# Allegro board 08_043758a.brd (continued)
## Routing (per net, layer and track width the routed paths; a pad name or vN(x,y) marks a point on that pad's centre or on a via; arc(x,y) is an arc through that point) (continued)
IO_L20_34_TX_D10: length 22.9
  TOP w0.102: v2(48.22,33.34) 48.23,33.35 U4.R8 ; U5.F8 v2(30.74,30.48)
  L6_SIG w0.114: v2(30.74,30.48) 30.75,30.48 31.14,30.88 31.14,31.68 31.48,32.02 31.68,32.02 32.14,32.48 35.15,32.48 35.89,33.22 44.51,33.22 45.06,32.68 45.06,32.28 45.19,32.15 47.79,32.15 48.06,31.88 48.36,31.88 48.76,32.28 48.76,32.8 v2(48.22,33.34)
IO_L20_34_TX_D11: length 22.6
  TOP w0.102: U5.E7 v2(31.54,31.28) ; v2(44.53,32.55) 46.03,34.05 48.23,34.05 48.32,34.15 U4.R7
  L6_SIG w0.114: v2(31.54,31.28) 31.54,31.68 31.65,31.78 31.85,31.78 32.31,32.24 35.73,32.24 35.87,32.38 35.87,32.54 36.02,32.68 36.23,32.68 36.37,32.54 36.37,32.38 36.52,32.24 36.72,32.24 36.87,32.38 36.87,32.54 37.01,32.68 37.22,32.68 37.36,32.54 37.36,32.38 37.51,32.24 37.71,32.24 37.86,32.38 37.86,32.54 38,32.68 38.21,32.68 38.35,32.54 38.35,32.38 38.5,32.24 38.7,32.24 38.85,32.38 38.85,32.54 38.99,32.68 39.2,32.68 39.34,32.54 39.34,32.26 39.49,32.11 39.69,32.11 39.84,32.26 39.84,32.54 39.98,32.68 40.19,32.68 40.33,32.54 40.33,32.24 40.49,32.08 44.4,32.08 44.53,32.21 v2(44.53,32.55)
IO_L21_34_CTRL_OUT4: length 32.1
  TOP w0.102: U5.F6 v2(29.95,32.88) ; U4.M10 v2(50.73,31.35)
  L5_SIG w0.114: v2(50.73,31.35) 51.13,30.95 51.13,30.34 50.93,30.14 48.93,30.14 48.26,29.47 46.91,29.47 45.93,30.45 45.53,30.45 44.02,31.95 44.02,32.85 43.26,33.61 43.26,34.38 41.27,36.38 36.57,36.38 35.28,37.67 32.1,37.67 31.6,37.16 31.6,36.73 31.14,36.28 31.14,33.47 30.95,33.28 30.35,33.28 v2(29.95,32.88)
IO_L21_34_CTRL_OUT5: length 30.6
  TOP w0.102: U4.M11 v2(50.73,30.55) ; U5.F5 v2(29.95,33.67)
  L5_SIG w0.114: v2(29.95,33.67) 30.34,34.07 30.34,34.68 29.95,35.08 29.95,36.65 31.72,38.43 40.55,38.43 45.23,33.75 45.23,32.31 45.69,31.85 46.33,31.85 47.03,31.15 47.03,30.88 47.36,30.54 47.93,30.54 48.34,30.95 50.33,30.95 v2(50.73,30.55)
IO_L22_34_CTRL_OUT6: length 32.3
  TOP w0.102: U5.F4 v2(29.94,34.48) ; v2(49.93,34.55) U4.N7
  L5_SIG w0.114: v2(29.94,34.48) 29.54,34.08 28.85,34.08 28.74,34.18 28.74,37.1 29.18,37.54 29.69,37.54 31.34,39.19 40.79,39.19 47.03,32.95 47.03,32.38 47.26,32.14 48.43,32.14 48.76,32.48 48.76,33.38 v2(49.93,34.55)
IO_L22_34_CTRL_OUT7: length 29.9
  TOP w0.102: v2(49.93,33.75) U4.N8 ; U5.G4 v2(29.14,34.48)
  L5_SIG w0.114: v2(29.14,34.48) 29.55,34.88 29.55,36.76 31.6,38.81 40.67,38.81 46.23,33.25 46.23,32.35 47.23,31.34 48.33,31.34 49.53,32.54 49.53,33.35 v2(49.93,33.75)
IO_L23_35_SPI_CLK: length 70.5
  TOP w0.102: U5.J5 v2(27.55,33.68) ; U4.E11 v2(57.13,30.55)
  L5_SIG w0.114: v2(27.55,33.68) 27.15,33.28 26.44,33.28 26.04,33.68 24.96,33.68 21.91,30.62 21.91,23.61 28.17,17.35 34.52,17.35 35.28,16.58 44.55,16.58 45.18,17.22 57.63,17.22 58.83,18.42 58.83,25.95 59.33,26.45 59.33,28.05 59.13,28.25 59.13,30.07 58.14,31.06 57.64,31.06 v2(57.13,30.55)
IO_L23_35_SPI_ENB: length 63.4
  TOP w0.102: U4.E12 v2(57.13,29.75) ; U5.K6 v2(26.74,32.88)
  L5_SIG w0.114: v2(57.13,29.75) 57.13,29.75 57.53,29.35 58.13,29.35 58.33,29.15 58.33,27.95 58.73,27.55 58.73,26.85 58.23,26.35 58.23,18.96 57.25,17.98 28.55,17.98 22.51,24.02 22.51,30.37 24.61,32.48 26.34,32.48 v2(26.74,32.88)
IO_L24_35_SPI_DI: length 64.3
  TOP w0.102: U4.E13 v2(57.13,28.95) ; U5.J4 v2(27.54,34.48)
  L5_SIG w0.114: v2(57.13,28.95) 57.13,28.95 57.93,28.15 57.93,19.17 57.12,18.36 28.67,18.36 22.8,24.24 22.8,30.24 22.99,30.43 23.2,30.43 23.42,30.21 23.63,30.21 23.77,30.35 23.77,30.56 23.55,30.78 23.55,30.99 24.21,31.65 26.31,31.65 26.61,31.94 27.51,31.94 27.94,32.38 U5.J4 v2(27.54,34.48)
IO_L24_35_SPI_DO: length 66.7
  TOP w0.102: U4.F12 v2(56.33,29.75) ; U5.L6 v2(25.95,32.88)
  L5_SIG w0.114: v2(25.95,32.88) 25.55,33.28 24.99,33.28 22.21,30.5 22.21,23.81 28.42,17.6 36.93,17.6 37.56,16.96 44.17,16.96 44.8,17.6 57.38,17.6 58.53,18.76 58.53,26.15 59.03,26.65 59.03,27.75 58.63,28.15 58.63,29.25 58.33,29.55 58.33,29.95 58.13,30.15 56.73,30.15 56.33,29.75 v2(56.33,29.75)
JTAG_TCK: length 44.5
  TOP w0.102: v1(70.34,31.82) 69.83,32.33 63.98,32.33 63.47,32.84 61.55,32.84 61.44,32.95 55.53,32.95 U4.G9 ; P1.4 66.01,9.34 v1(68.82,9.34)
  L5_SIG w0.114: v1(68.82,9.34) 68.82,19.14 69.83,20.15 69.83,31.32 v1(70.34,31.82)
JTAG_TDI: length 38.9
  TOP w0.102: U4.L7 v2(51.53,34.55)
  L5_SIG w0.114: P1.8 65,9.09 62.58,9.09 61.85,9.83 61.85,23.42 61.06,24.2 61.06,31.06 59.07,33.05 55.63,33.05 54.53,34.15 51.92,34.15 51.53,34.54 v2(51.53,34.55)
JTAG_TDO: length 37.5
  TOP w0.102: U4.L8 v2(51.53,33.75)
  L5_SIG w0.114: v2(51.53,33.75) 51.53,33.74 51.92,33.35 54.93,33.35 55.53,32.75 58.93,32.75 59.93,31.75 59.93,30.27 60.23,29.97 60.23,29.49 60.68,29.04 60.68,23.95 61.47,23.16 61.47,9.45 62.33,8.58 64.23,8.58 P1.6
JTAG_TMS: length 34.5
  TOP w0.102: U4.L9 v2(51.53,32.95)
  L5_SIG w0.114: v2(51.53,32.95) 52.73,31.75 59.13,31.75 59.53,31.35 59.53,30.31 59.92,29.93 59.92,29.22 60.3,28.84 60.3,23.7 61.09,22.91 61.09,9.19 P1.2
PG_1P0V: length 28.6
  TOP w0.203: U6.28 v2(93.7,46.94)
  TOP w0.305: U3.16 92.57,21.55 v1(92.94,21.92)
  L6_SIG w0.254: v1(92.94,21.92) 93.7,22.68 93.7,46.93 v2(93.7,46.94)
  BOTTOM w0.305: R6.2 v1(92.94,21.92)
PG_1P8V: length 12.7
  TOP w0.203: U6.29 94.2,47.27 v2(94.32,46.92) ; U6.13 v2(93.7,54.05)
  L5_SIG w0.305: v2(94.32,46.92) 94.32,47.3 96.11,49.1 96.11,52.52 95.48,53.16 94.21,53.16 93.7,53.66 v2(93.7,54.05)
  BOTTOM w0.305: v2(94.32,46.92) R59.1
PS-SRST#: length 30.4
  TOP w0.127: v1(71.23,29.41) 70.09,29.41 68.57,30.93 64.11,30.93 63.98,30.81 63.98,30.54 R74.2 61.95,30.3 60.91,31.34 59.52,31.34 U4.B11
  L5_SIG w0.127: v1(74.65,42.75) 75.54,41.86 75.54,33.08 71.87,29.41 v1(71.23,29.41)
  BOTTOM w0.127: R11.2 v1(74.65,42.75)
PS_MIO01_500_QSPI0_SS_B: length 37
  TOP w0.127: U13.C2 v2(72.61,48.31) ; U4.A5 60.54,35.75 61.31,36.52 65.25,36.52 65.89,37.16 v1(65.89,40.08)
  L5_SIG w0.127: v1(65.89,40.08) 68.81,43 68.81,49.98 69.06,50.24 69.44,50.24 69.59,50.09 69.59,48.99 69.74,48.84 69.95,48.84 70.1,48.99 70.1,50.09 70.25,50.24 70.46,50.24 70.61,50.09 70.61,48.99 70.76,48.84 70.97,48.84 71.11,48.99 71.11,50.09 71.26,50.24 71.47,50.24 71.62,50.09 71.62,48.74 71.77,48.59 71.98,48.59 72.13,48.74 72.13,50.09 72.28,50.24 73.25,50.24 73.63,49.86 73.63,49.33 v2(72.61,48.31)
  BOTTOM w0.127: R14.2 72.62,48.32 v2(72.61,48.31)
PS_MIO02_500_QSPI0_IO0: length 33.4
  TOP w0.127: U4.A8 61.43,33.35 61.56,33.22 63.73,33.22 63.85,33.35 69.71,33.35 70.47,32.59 73.12,32.59 v1(74.14,33.6) ; U13.D3 v2(70.61,47.31)
  L5_SIG w0.127: v2(70.61,47.31) 72.24,45.68 72.24,41.98 72.47,41.75 72.68,41.75 72.91,41.98 73.13,41.98 73.27,41.83 73.27,41.62 73.04,41.39 73.04,41.18 73.27,40.95 73.48,40.95 73.65,41.12 73.86,41.12 74.01,40.97 74.01,40.76 73.84,40.59 73.84,40.38 74.14,40.08 v1(74.14,33.6)
  BOTTOM w0.127: v2(70.61,47.31) 69.93,47.31 R120.1
PS_MIO03_500_QSPI0_IO1: length 38
  TOP w0.127: U4.A7 60.36,33.72 v2(61.65,33.72) ; U13.D2 v2(70.61,48.31)
  L5_SIG w0.127: v2(70.61,48.31) 69.54,48.31 69.19,47.95 69.19,47.59 69.34,47.44 69.8,47.44 69.95,47.29 69.95,47.08 69.8,46.93 69.34,46.93 69.19,46.78 69.19,41.92 69.04,41.77 68.32,41.77 68.17,41.62 68.17,41.41 68.32,41.26 69.04,41.26 69.19,41.11 69.19,40.9 69.04,40.75 68.32,40.75 68.17,40.6 68.17,40.39 68.32,40.24 69.04,40.24 69.19,40.1 69.19,39.82 68.81,39.44 67.66,39.44 66.77,38.55 66.77,38.09 68.02,36.84 68.02,36.63 67.87,36.48 67.66,36.48 66.41,37.73 66.2,37.73 66.05,37.58 66.05,37.37 66.67,36.75 66.67,36.54 66.52,36.39 66.31,36.39 65.69,37.01 65.48,37.01 65.33,36.86 65.33,36.65 65.95,36.03 65.95,35.82 65.8,35.67 65.59,35.67 64.97,36.29 64.76,36.29 64.61,36.14 64.61,35.93 65.23,35.32 65.23,35.1 65.08,34.96 64.87,34.96 64.26,35.57 64.05,35.57 63.09,34.62 61.95,34.62 61.65,34.32 v2(61.65,33.72)
  BOTTOM w0.127: R119.1 69.91,48.31 v2(70.61,48.31)
PS_MIO04_500_QSPI0_IO2: length 35.9
  TOP w0.127: U4.C8 v2(57.93,33.75) ; U13.C4 v2(71.59,45.29)
  L5_SIG w0.127: v2(71.59,45.29) 70.97,45.92 70.46,45.92 69.57,45.03 69.57,42.36 70.08,41.86 70.08,37.67 69.66,37.25 69.66,37.04 70.4,36.3 70.4,36.09 70.25,35.94 70.04,35.94 69.3,36.68 69.09,36.68 68.91,36.5 68.91,36.29 69.59,35.61 69.59,35.4 69.44,35.25 69.23,35.25 68.55,35.93 68.34,35.93 68.19,35.78 68.19,35.57 68.87,34.89 68.87,34.68 68.72,34.53 68.51,34.53 67.83,35.21 67.62,35.21 67.47,35.06 67.47,34.85 68.15,34.17 68.15,33.96 68,33.81 67.79,33.81 67.11,34.49 64.11,34.49 62.84,33.22 61.31,33.22 60.17,34.36 58.54,34.36 v2(57.93,33.75)
  BOTTOM w0.127: v2(71.59,45.29) 71.6,45.29 R121.1
PS_MIO05_500_QSPI0_IO3: length 68.4
  TOP w0.127: v1(70.34,30.93) 69.33,31.95 63.85,31.95 63.26,32.55 U4.A9 ; P1.5 v1(65.38,4.65) ; U13.D4 v2(70.61,45.31)
  L5_SIG w0.127: v2(70.61,45.31) 69.95,44.65 69.95,42.62 70.37,42.2 71.13,42.2 71.28,42.05 71.28,41.84 70.86,41.41 70.86,41.2 71.01,41.06 71.22,41.06 71.64,41.48 71.85,41.48 72,41.33 72,41.12 71.57,40.7 71.57,40.49 71.72,40.34 71.93,40.34 72.36,40.76 72.57,40.76 72.72,40.61 72.72,40.4 72.29,39.98 72.29,39.77 72.47,39.59 72.68,39.59 73.17,40.07 73.38,40.07 73.53,39.93 73.53,39.72 73.04,39.23 73.04,39.02 73.63,38.43 73.63,33.14 72.54,32.05 71.46,32.05 v1(70.34,30.93) 70.34,19.77 69.31,18.74 69.31,9.99 69.71,9.6 69.71,5.28 69.07,4.65 v1(65.38,4.65)
  BOTTOM w0.127: R122.1 70.61,44.54 v2(70.61,45.31)
PS_MIO06_500_QSPI0_SCLK: length 34.4
  TOP w0.127: v1(72.12,30.93) 71.23,30.05 69.96,30.05 68.82,31.19 63.6,31.19 63.04,31.75 U4.A10 ; U13.B2 v2(73.61,48.31)
  L5_SIG w0.127: v1(72.12,30.93) 74.65,33.46 74.65,41.22 72.74,43.13 72.74,47.44 v2(73.61,48.31)
  BOTTOM w0.127: R116.1 73.61,49.08 v2(73.61,48.31)
PS_MIO07_500_USB_RESET_B: length 20.5
  TOP w0.127: U4.A12 v2(60.58,30.15) ; v1(76.05,30.81) 77.3,29.55 U15.27
  L6_SIG w0.127: v1(76.05,30.81) 73.12,30.81 72.74,30.43 61.57,30.43 61.29,30.15 v2(60.58,30.15)
  BOTTOM w0.127: v2(60.58,30.15) 60.02,30.15 R76.2
PS_MIO28_501_USB0_D4: length 23.7
  TOP w0.102: v1(66.65,24.58) 66.39,24.84 66.14,24.84 64.11,26.87 61.44,26.87 60.56,27.75 U4.A15 ; v1(73.25,24.48) U15.7
  L6_SIG w0.114: v1(73.25,24.48) 73.74,24.97 74.14,24.97 74.27,24.84 74.27,24.33 73.25,23.31 65.5,23.31 65.25,23.57 65.25,24.46 65.5,24.71 65.76,24.71 66.01,24.46 66.01,24.08 66.14,23.95 66.52,23.95 66.65,24.08 v1(66.65,24.58)
PS_MIO29_501_USB0_DIR: length 24.6
  TOP w0.102: v1(74.27,30.17) 75.3,29.14 U15.31 ; U4.D11 v2(57.93,30.55)
  L6_SIG w0.114: v2(57.93,30.55) 59.9,30.55 60.17,30.28 60.17,29.88 61.14,28.9 63.41,28.9 63.56,28.76 63.56,28.29 63.7,28.14 63.91,28.14 64.05,28.29 64.05,28.76 64.2,28.9 64.4,28.9 64.55,28.76 64.55,28.29 64.69,28.14 64.9,28.14 65.04,28.29 65.04,28.76 65.19,28.9 65.39,28.9 65.54,28.76 65.54,28.29 65.68,28.14 65.89,28.14 66.03,28.29 66.03,28.76 66.18,28.9 70.2,28.9 70.58,28.52 71.35,28.52 73,30.17 v1(74.27,30.17)
PS_MIO30_501_USB0_STP: length 25.2
  TOP w0.102: v1(67.41,23.95) 66.52,23.95 63.98,26.49 61.31,26.49 60.55,27.25 59.62,27.25 U4.B15 ; U15.29 76.3,29.53 75.66,30.17 v1(75.28,30.17)
  L6_SIG w0.114: v1(67.41,23.95) 67.79,23.95 68.04,23.7 71.6,23.7 72.74,24.84 72.74,25.85 73.25,26.36 74.01,26.36 75.28,27.63 v1(75.28,30.17)
PS_MIO31_501_USB0_NXT: length 23.6
  TOP w0.102: U15.2 73.4,26.98 v1(72.87,27.51) ; U4.C12 v2(58.73,29.75)
  L6_SIG w0.114: v1(72.87,27.51) 72.36,28.01 66.39,28.01 66.01,27.63 65.52,27.63 65.38,27.49 65.38,26.89 65.23,26.74 65.03,26.74 64.88,26.89 64.88,27.49 64.74,27.63 64.53,27.63 64.39,27.49 64.39,26.89 64.24,26.74 64.04,26.74 63.89,26.89 63.89,27.49 63.75,27.63 63.54,27.63 63.4,27.49 63.4,26.89 63.25,26.74 63.05,26.74 62.9,26.89 62.9,27.49 62.76,27.63 62.55,27.63 62.41,27.49 62.41,26.89 62.26,26.74 62.06,26.74 61.91,26.89 61.91,27.49 61.77,27.63 60.04,27.63 58.73,28.95 v2(58.73,29.75)
PS_MIO32_501_USB0_D0: length 24.3
  TOP w0.102: v1(64.74,23.44) 63.22,24.97 60.55,24.97 60.3,25.22 58.39,25.22 56.73,26.88 U4.E15 ; v1(71.98,27.47) 71.98,26.71 72.21,26.48 U15.3
  L6_SIG w0.114: v1(64.74,23.44) 64.74,24.46 65.76,25.47 66.65,25.47 67.03,25.85 67.03,26.36 66.52,26.87 66.52,27.25 66.74,27.47 v1(71.98,27.47)
PS_MIO33_501_USB0_D1: length 24
  TOP w0.102: U4.C11 58.74,30.54 60.69,30.54 60.72,30.52 60.73,30.52 60.95,30.3 60.95,30.29 61.95,29.28 63.98,29.28 64.23,29.03 65.89,29.03 67.53,27.39 v1(67.53,26.1) ; U15.4 71.73,25.98 v1(71.22,26.49)
  L6_SIG w0.114: v1(67.53,26.1) 67.53,26.99 67.66,27.12 67.89,27.12 68.03,26.98 68.03,26.51 68.18,26.36 68.39,26.36 68.53,26.51 68.53,26.98 68.68,27.12 68.88,27.12 69.03,26.98 69.03,26.51 69.17,26.36 69.38,26.36 69.52,26.51 69.52,26.98 69.67,27.12 69.95,27.12 70.08,27 70.08,26.36 70.2,26.24 70.46,26.24 70.58,26.36 70.58,26.87 70.84,27.12 71.09,27.12 71.22,27 v1(71.22,26.49)
PS_MIO34_501_USB0_D2: length 25.3
  TOP w0.102: v1(65.38,22.43) 65.38,23.57 63.6,25.35 60.93,25.35 60.17,26.11 58.29,26.11 57.53,26.87 U4.D15 ; v1(73.25,25.48) U15.5
  L6_SIG w0.114: v1(65.38,22.43) 65.89,22.93 74.39,22.93 74.7,23.24 74.7,25.17 74.39,25.48 v1(73.25,25.48)
PS_MIO35_501_USB0_D3: length 23.7
  TOP w0.102: v1(71.22,25.47) 71.72,24.98 U15.6 ; U4.A14 60.78,28.55 61.69,27.63 64.36,27.63 66.39,25.6 68.3,25.6 v1(68.81,25.09)
  L6_SIG w0.114: v1(68.81,25.09) 68.3,25.09 68.04,25.35 68.04,25.73 68.17,25.85 69.31,25.85 69.44,25.73 69.44,24.84 69.57,24.71 69.94,24.71 70.08,24.86 70.08,25.71 70.23,25.85 70.43,25.85 70.58,25.71 70.58,24.86 70.72,24.71 71.47,24.71 71.98,25.22 71.98,25.83 71.83,25.98 71.35,25.98 71.22,25.85 v1(71.22,25.47)
PS_MIO36_501_USB0_CLK: length 23.1
  TOP w0.102: v1(67.41,25.09) 66.77,25.09 66.65,25.22 66.27,25.22 64.23,27.25 61.57,27.25 60.68,28.14 59.54,28.14 U4.B14 ; U15.1 v1(74.1,28.14)
  L6_SIG w0.114: v1(67.41,25.09) 68.43,24.08 68.76,24.08 69.01,24.33 69.25,24.33 69.5,24.08 69.75,24.08 70,24.33 70.24,24.33 70.5,24.08 71.35,24.08 72.36,25.09 72.36,26.49 72.62,26.74 73.89,26.74 74.9,27.76 74.9,28.52 74.78,28.65 74.23,28.65 74.1,28.52 v1(74.1,28.14)
PS_MIO37_501_USB0_D5: length 24.4
  TOP w0.102: v1(66.39,22.43) 66.39,23.57 63.85,26.11 61.19,26.11 60.42,26.87 59.15,26.87 58.7,27.33 58.7,28.18 U4.C14 ; v1(74.14,22.43) 74.52,22.43 74.8,22.71 U15.9
  L6_SIG w0.114: v1(74.14,22.43) 73.34,22.43 73.19,22.28 73.19,21.94 73.05,21.79 72.84,21.79 72.7,21.94 72.7,22.28 72.55,22.43 72.35,22.43 72.2,22.28 72.2,21.94 72.06,21.79 71.85,21.79 71.71,21.94 71.71,22.28 71.56,22.43 71.36,22.43 71.21,22.28 71.21,21.94 71.07,21.79 70.86,21.79 70.72,21.94 70.72,22.28 70.57,22.43 70.37,22.43 70.22,22.28 70.22,21.94 70.08,21.79 67.54,21.79 66.9,22.43 v1(66.39,22.43)
PS_MIO38_501_USB0_D6: length 25.5
  TOP w0.102: U4.A13 60.33,28.95 60.89,28.95 61.82,28.01 64.62,28.01 v1(66.52,26.11) ; U15.10 75.3,22.57 v1(74.14,21.41)
  L6_SIG w0.114: v1(66.52,26.11) 65.89,26.11 64.23,24.46 64.23,22.55 64.87,21.92 66.65,21.92 67.16,21.41 v1(74.14,21.41)
PS_MIO39_501_USB0_D7: length 25.5
  TOP w0.102: U4.D14 57.96,28.12 57.96,27 58.47,26.49 60.3,26.49 61.06,25.73 63.73,25.73 65.89,23.57 65.89,21.92 v1(66.39,21.41) ; U15.13 76.8,22.53 v1(76.58,22.3)
  L6_SIG w0.114: v1(76.58,22.3) 75.18,20.9 66.9,20.9 v1(66.39,21.41)
PWR_GD: length 23.9
  TOP w0.203: v1(23.23,9.85) R5.2 22.58,10.61 22.28,10.91 U1.5 ; U7.5 v1(43.15,10.23)
  BOTTOM w0.127: v1(23.23,9.85) 28.93,9.85 29.69,9.09 42,9.09 v1(43.15,10.23)
PWR_GD_1.35V: length 59.4
  TOP w0.127: U4.C9 58.73,32.15 63.15,32.15 63.73,31.57 68.95,31.57 70.09,30.43 70.72,30.43 v1(71.23,30.93)
  TOP w0.203: v2(94.33,54.05) 94.2,53.66 U6.12
  L5_SIG w0.127: v2(94.33,54.05) 93.86,54.52 92.21,54.52 91.15,53.46 88.85,53.46 85.17,49.78 85.17,46.58 76.05,37.45 76.05,32.85 71.94,28.74 71.04,28.74 70.74,29.04 70.74,29.85 71.23,30.34 v1(71.23,30.93)
  BOTTOM w0.127: R13.2 72.95,32.01 C47.1 71.52,32.01 R15.1 71.23,31.7 v1(71.23,30.93)
REF_CLK_SG: length 81.4
  TOP w0.127: R50.1 23.21,21.14 v1(23.21,19.38) ; R10.1 63.36,35.63 v1(66.52,35.63)
  BOTTOM w0.127: v1(66.52,35.63) 67.61,34.54 74.47,34.54 74.78,34.24 74.78,25.09 65.76,16.08 46.99,16.08 44.19,18.87 37.44,18.87 36.8,18.23 26.9,18.23 25.75,19.38 v1(23.21,19.38)
RX1A_N: length 2.6
  TOP w0.229: C133.2 arc(23.54,36.54) 23.84,36.45 24.33,36.09 arc(24.64,35.93) 24.99,35.87 25.18,35.87 arc(25.38,35.82) U5.M2
RX1A_P: length 2.5
  TOP w0.229: C134.2 arc(23.72,37.31) 23.71,37.23 arc(23.76,37.06) 23.87,36.93 24.57,36.42 arc(24.77,36.32) 24.99,36.28 25.35,36.28 arc(25.49,36.34) U5.M1
SCL: length 45.4
  TOP w0.102: v2(49.53,26.05) 50.25,26.77 50.52,26.77 50.73,26.98 50.73,28.15 U4.M14
  TOP w0.127: v1(51.03,16.58) 51.53,17.09 52.55,17.09 52.93,16.71 52.93,15.34 55.24,13.03 56.6,13.03 R79.2 57.29,13.61 U11.2 60.24,13.61 60.81,14.17 60.81,15.19 64.23,18.62 65,18.62 v1(65.5,19.12)
  BOTTOM w0.127: v1(51.03,16.58) 51.03,22.93 50.23,23.73 50.23,25.34 49.53,26.04 v2(49.53,26.05) ; v1(65.5,19.12) 65.5,20.27 64.36,21.41 63.22,21.41 61.31,23.31 61.31,26.87 R86.2
SDA: length 44.5
  TOP w0.102: U4.N14 49.93,28.15 49.93,27.25 v2(49.53,26.85)
  TOP w0.127: v1(65.5,18.11) 64.36,18.11 61.31,15.06 61.31,14.04 60.23,12.96 U11.3 57.81,12.96 57.63,12.77 57.63,12.41 R78.2 56.6,12.65 54.92,12.65 52.23,15.34 v1(52.23,16.58)
  BOTTOM w0.127: v1(52.23,16.58) 51.41,17.41 51.41,23.06 50.63,23.84 50.63,25.75 v2(49.53,26.85) ; v1(65.5,18.11) 64.87,18.74 64.87,20.01 63.85,21.03 62.96,21.03 61.06,22.93 61.06,26.36 60.68,26.74 R85.2
SYNC: length 9.2
  TOP w0.305: 88.37,18.6 U3.9 ; U3.9 U3.10 ; U3.9 88.81,17.85 ; U3.10 U3.11 90.11,17.85 ; U3.10 89.46,17.85
  TOP w0.889: L4.1 88.58,16.9 ; L4.1 88.58,12.71 ; L4.1 89.57,14.81
TX1A_N: length 3.8
  TOP w0.229: L8.2 22.65,29.83 arc(22.91,30.01) 23.22,30.07 23.56,30.07 arc(23.88,30.13) 24.16,30.32 24.79,30.95 arc(24.94,31.05) 25.11,31.08 25.23,31.08 arc(25.33,31.06) 25.42,31 U5.M8
TX1A_P: length 3.8
  TOP w0.229: U5.M7 25.44,31.57 arc(25.35,31.51) 25.23,31.49 25.11,31.49 arc(24.78,31.42) 24.5,31.23 23.87,30.6 arc(23.73,30.51) 23.56,30.47 23.22,30.47 arc(22.91,30.54) 22.64,30.72 L9.2
TX_VCO_1P1V_SUPPLY: length 3.4
  TOP w0.305: U5.B11 v2(33.94,28.08) ; U5.A11 v2(34.74,28.08)
  BOTTOM w0.305: R52.1 C128.1 35.16,28.08 v2(34.74,28.08)
  BOTTOM w0.406: v2(33.94,28.08) v2(34.74,28.08)
UART_RX: length 42.6
  TOP w0.127: U4.C6 v2(57.93,35.35) ; P1.1 61.95,7.06 61.95,8.07 62.84,8.96 v1(62.84,9.73)
  L5_SIG w0.127: v2(57.93,35.35) 57.53,34.95 57.53,33.55 57.73,33.35 59.28,33.35 60.93,31.7 64.87,31.7 66.52,30.05 66.52,27.38 65.5,26.36 65.5,24.23 67.66,22.08 67.66,14.55 67.03,13.92 64.11,13.92 62.84,12.65 v1(62.84,9.73)
UART_TX: length 40.5
  TOP w0.127: U4.B7 v2(59.53,33.75)
  L5_SIG w0.127: v2(59.53,33.75) 59.53,33.75 60.95,32.33 65.38,32.33 67.92,29.79 67.92,28.52 68.3,28.14 68.3,8.71 68.93,8.07 68.93,5.66 68.55,5.28 65,5.28 P1.3
UNNAMED_2_ADP1754_I93_SS: length 1.5
  TOP w0.203: C2.1 23.08,12.21 U1.7
UNNAMED_2_ADP1754_I233_SS: length 1.5
  TOP w0.203: U7.7 44.67,12.21 C12.1
UNNAMED_2_ADP2164_I29_EN: length 13.4
  TOP w0.305: 92.99,20.2 R1.1 ; R1.1 93.44,20.61 ; R1.1 93.9,20.2 ; 90.89,24.2 90.76,24.07 U3.1 ; C13.1 89.46,24.16 U3.3 ; 92.5,20.9 U3.15 U3.14 92.5,20.25
  TOP w0.508: C13.1 89.52,24.2 91.79,24.2 93.95,22.04 93.95,20.9
UNNAMED_2_ADP2164_I29_PVIN1: length 11.6
  TOP w0.305: R1.2 93.9,19.57 ; R1.2 93.44,19.16 ; R1.2 92.99,19.57 ; 91.75,19.16 U3.13 92.5,19.6 ; 91.19,18.6 U3.12 90.76,17.85
  TOP w0.762: L1.2 95.22,17.97 ; L1.2 95.22,15.45 ; L1.2 94.34,16.71
  TOP w1.016: C11.1 92.68,16.28 ; C11.1 91.63,15.38 ; C11.1 93.74,15.38
  BOTTOM w0.305: R6.1 93.58,19.5 v1(94.21,19.5)
UNNAMED_2_ADP2164_I29_RT: length 1.8
  TOP w0.305: v1(90.11,23.57) U3.2
  BOTTOM w0.305: R3.2 90.12,23.56 v1(90.11,23.57)
UNNAMED_2_RES_I251_N2: length 1.4
  BOTTOM w0.305: R4.2 R7.1
UNNAMED_3_ICN25Q256AV2_I26_RESE: length 1.5
  TOP w0.127: v2(74.65,45.27) U13.A4
  BOTTOM w0.127: R11.1 v2(74.65,45.27)
UNNAMED_3_ICXC7Z010_I16_PSCLK50: length 6.8
  TOP w0.127: R10.2 63.17,34.55 58.73,34.55 U4.C7
  TOP w0.305: R12.2 63.46,34.74 R10.2
UNNAMED_3_ICXC7Z010_I16_PSMIO75: length 4.9
  TOP w0.127: U4.D9 v2(57.93,32.15)
  BOTTOM w0.127: R83.2 61.74,32.45 58.23,32.45 v2(57.93,32.15)
UNNAMED_3_ICXC7Z010_I16_PSMIO85: length 8.9
  TOP w0.127: R84.1 66.65,37.03 65.76,36.14 61.57,36.14 60.78,35.35 59.54,35.35 U4.B6
UNNAMED_3_RES_I2_N1: length 2.5
  TOP w0.305: R9.1 71.6,36.15 R8.2 70.15,36.14 Y2.1
UNNAMED_3_RES_I48_N1: length 2.4
  TOP w0.305: R12.1 68.18,34.74 Y2.3
UNNAMED_4_ICMT41K256M16_I98_ZQ: length 4.2
  TOP w0.127: v2(52.82,46.57) 52.82,49.47 U2.L8
  BOTTOM w0.165: R165.1 52.82,45.86 v2(52.82,46.57)
UNNAMED_4_ICTPS51206_I44_S3: length 1.8
  TOP w0.127: U14.7 36.35,53.43 v2(36.24,53.54)
  BOTTOM w0.127: v2(36.24,53.54) 36.55,53.24 36.55,53.02 R222.2
UNNAMED_4_ICTPS51206_I44_S5: length 3.7
  TOP w0.127: v1(34.77,52.14) 35.26,52.63 U14.9
  BOTTOM w0.127: v1(34.77,52.14) 35.15,52.52 35.55,52.52 R221.2
UNNAMED_4_ICTPS51206_I44_VLDOIN: length 2.6
  TOP w0.203: 39.86,52.63 U14.2
  TOP w0.508: R44.2 41.3,51.88 ; R44.2 40.74,52.44 ; R44.2 40.18,51.88
UNNAMED_4_ICTPS51206_I44_VTTSNS: length 3
  TOP w0.203: U14.5 39.51,53.83 v2(39.85,54.18)
  BOTTOM w0.305: R43.2 41.2,54.87 C80.1 39.85,54.49 v2(39.85,54.18)
UNNAMED_4_ICXC7Z010_I26_PSDDR_1: length 3.4
  TOP w0.127: U4.H3 v2(54.73,37.75)
  BOTTOM w0.127: R40.1 54.33,39.76 54.33,38.15 v2(54.73,37.75)
UNNAMED_4_ICXC7Z010_I26_PSDDRVR: length 1.2
  TOP w0.127: U4.J3 v2(53.13,37.75)
  BOTTOM w0.127: v2(53.13,37.75) 53.22,37.66 R41.1
UNNAMED_5_CAP_I17_N1: length 20.5
  TOP w0.305: U4.F7 v2(55.53,34.55)
  L6_SIG w0.305: 58.49,33.19 56.65,33.19 56.36,33.47 56.36,34.24 56.05,34.55 v2(55.53,34.55)
  L6_SIG w0.508: v1(66.66,40.09) 66.66,39.71 65.12,38.17 65.12,36.9 63.09,34.87 63.09,33.86 62.28,33.05 58.63,33.05 58.49,33.19
  BOTTOM w0.305: C98.1 55.84,34.23 v2(55.53,34.55)
  BOTTOM w0.508: C93.1 v1(66.66,40.09)
  BOTTOM w0.635: C93.1 66.66,41.93 E5.2
UNNAMED_5_CAP_I17_N2: length 27
  TOP w0.305: U4.J7 v2(53.93,33.75) U4.H7 ; U4.G8 v2(55.53,33.75) U4.F8 ; U4.F6 v2(56.33,35.35)
  L5_SIG w0.406: v2(55.53,33.75) 56.33,34.55 v2(56.33,35.35)
  L6_SIG w0.305: v2(55.53,33.75) 55.53,33.42 56.23,32.71 58.07,32.71 58.53,32.25 58.73,32.25
  L6_SIG w0.508: 58.73,32.25 62.75,32.25 64.11,33.6 64.11,34.62 66.77,37.28 66.77,38.68 67.65,39.56 v1(67.65,40.08) ; v2(55.53,33.75) v2(53.93,33.75)
  BOTTOM w0.305: C98.2 56.33,35.34 v2(56.33,35.35)
  BOTTOM w0.508: v1(67.65,40.08) C93.2
  BOTTOM w0.635: C93.2 E6.2
UNNAMED_5_DIOLED_I60_N: length 2.7
  TOP w0.127: DS1.C v1(106.78,21.49)
  BOTTOM w0.127: v1(106.78,21.49) 106.44,21.16 R48.1
UNNAMED_5_DIOLED_I62_N: length 2.7
  TOP w0.127: DS2.C v1(106.91,13.11)
  BOTTOM w0.127: R87.1 106.57,12.77 v1(106.91,13.11)
UNNAMED_5_ICXC7Z010_I13_DONE0: length 68.5
  TOP w0.127: U4.M7 v2(50.73,34.55)
  L6_SIG w0.127: v1(101.95,16.58) 99.46,14.09 90.35,14.09 86.25,18.19 86.25,25.64 81.75,30.15 79.55,30.15 76.84,32.85 70.14,32.85 69.04,31.75 53.53,31.75 52.73,32.55 52.73,33.95 52.53,34.15 51.12,34.15 50.73,34.53 v2(50.73,34.55)
  BOTTOM w0.127: v1(101.95,16.58) 101.95,17.65 Q1.1
UNNAMED_5_ICXC7Z010_I13_INITB0: length 8.3
  TOP w0.127: R47.1 64.48,36.9 61.06,36.9 60.3,36.15 57.93,36.15 U4.D5
UNNAMED_5_ICXC7Z010_I13_PROGRAM: length 4
  TOP w0.127: U4.K6 v2(52.33,35.35)
  BOTTOM w0.127: R46.1 51.13,33.44 51.13,34.95 51.53,35.35 52.33,35.35 v2(52.33,35.35)
UNNAMED_5_ICXC7Z010_I13_VCCBATT: length 5.2
  TOP w0.127: U4.E6 v2(57.13,35.35)
  BOTTOM w0.127: v2(57.13,35.35) 57.53,34.94 57.53,34.35 57.73,34.15 59.74,34.15 59.93,33.95 59.93,33.05 R45.2
UNNAMED_5_RES_I61_N2: length 2.6
  BOTTOM w0.127: R48.2 104.25,18.65 Q1.3
UNNAMED_5_RES_I63_N2: length 2.6
  BOTTOM w0.127: R87.2 104.21,12.74 Q4.3
UNNAMED_7_AD9363_I13_RBIAS: length 3.7
  TOP w0.178: 25.14,33.68 25.94,33.68
  TOP w0.305: 25.94,33.68 U5.L4
  TOP w0.406: R49.2 23.6,34.16 arc(24.14,33.8) 24.78,33.68 25.14,33.68
UNNAMED_7_AD9363_I13_XTALN: length 4.5
  TOP w0.203: U5.M12 24.93,27.06 C124.1 24.93,23.57 C123.2
UNNAMED_7_CAP_I22_N2: length 1
  BOTTOM w0.305: C126.2 R51.1
UNNAMED_7_CAP_I30_N1: length 1
  BOTTOM w0.305: C127.1 36.15,26.38 R52.2
UNNAMED_7_CAP_I39_N2: length 2.2
  TOP w0.483: T5.4 arc(19.12,31.31) C132.2
UNNAMED_7_CAP_I40_N2: length 2.2
  TOP w0.483: T5.6 arc(19.12,29.22) C131.2
UNNAMED_7_CAP_I51_N1: length 2.2
  TOP w0.483: T1.4 22.98,38.26 arc(23.15,38.01) C134.1
UNNAMED_7_CAP_I52_N1: length 2.2
  TOP w0.483: C133.1 22.68,36.76 22.18,36.76 arc(21.38,36.86) T1.6
UNNAMED_7_CAP_I53_N1: length 2.8
  TOP w0.203: Y3.3 24.98,20.15 R50.2 24.99,21.93 C123.1
UNNAMED_7_CNBNC5P_I55_CNTR: length 16.7
  TOP w0.483: RX1A.1 8.73,46.39 arc(9.67,46.27) 10.55,45.9 12.3,44.89 T1.3
UNNAMED_7_CNBNC5P_I56_CNTR: length 16.9
  TOP w0.483: T5.3 13.48,31.54 arc(11.3,30.64) 10.41,28.47 10.41,26 arc(10.21,25.03) 9.67,24.21 9.08,23.62 arc(8.33,23.12) 7.44,22.95 TX1A.1
UNNAMED_9_ADM1177_I23_GATE: length 2.1
  TOP w0.305: 89.37,35.75 U10.10
  TOP w0.635: 89.6,33.65 Q3.1 88.64,34.41
UNNAMED_9_ADM1177_I23_ON: length 3
  TOP w0.203: R71.2 95.46,37.16 U10.3
  TOP w0.254: R72.1 95.62,37.03 R71.2
UNNAMED_9_ADM1177_I23_SENSE: length 9.4
  TOP w0.305: 92.17,33.86 92.17,36.27 92.56,36.66 U10.2
  TOP w0.762: Q3.3 90.88,33.48 ; Q3.3 91.83,32.71 ; Q3.3 90.88,31.95 ; 93.13,31.76 R73.2 ; R73.2 93.13,33.67 ; R73.2 92.23,32.71
UNNAMED_9_ADM1177_I23_SS: length 1.9
  TOP w0.305: C155.1 88.24,36.66 U10.9
UNNAMED_9_ADM1177_I23_TIMER: length 2.5
  TOP w0.203: C156.1 95.49,38.94 94.08,38.94 93.71,38.57 U10.5
UNNAMED_9_ADP2114_I196_FREQ: length 1.6
  TOP w0.305: U6.3 98.02,49.74 R53.2
UNNAMED_9_ADP2114_I196_OPCFG: length 1.8
  TOP w0.305: U6.6 97.14,51.24 v1(97.25,51.13)
  BOTTOM w0.508: R54.1 96.38,51.13 v1(97.25,51.13)
UNNAMED_9_ADP2114_I196_SS1: length 1.9
  TOP w0.203: v2(94.97,46.94) 94.7,47.32 U6.30
  BOTTOM w0.305: C7.2 94.97,47.46 v2(94.97,46.94)
UNNAMED_9_ADP2114_I196_SS2: length 1.9
  TOP w0.203: U6.11 94.7,53.67 v2(94.97,54.05)
  BOTTOM w0.305: v2(94.97,54.05) 94.97,53.53 C139.2
UNNAMED_9_ADP2114_I196_SW1: length 7.3
  TOP w0.305: 90.8,48.74 U6.24 91.41,48.65 91.41,48.46 91.16,48.21 ; 90.8,49.24 U6.23
  TOP w0.762: L3.1 88.11,48.78 ; L3.1 90.21,47.79 ; L3.1 86.01,47.79
UNNAMED_9_ADP2114_I196_SW3: length 7.2
  TOP w0.305: 90.8,52.24 U6.17 91.39,52.36 91.39,52.57 91.19,52.77 ; 90.8,51.74 U6.18
  TOP w0.762: 88.11,52.08 L2.1 ; L2.1 90.21,53.07 ; L2.1 86.01,53.07
UNNAMED_9_CAP_I163_N1: length 11.7
  TOP w0.762: 88.05,40.8 C146.1 ; C146.1 88.05,42.91 ; C146.1 87.15,41.86 ; L5.1 85.79,43.09 ; L5.1 86.56,41.73 ; L5.1 85.79,40.37 ; 88.11,44.33 L3.2 ; L3.2 90.21,45.32 ; L3.2 86.01,45.32
UNNAMED_9_CAP_I214_N2: length 1
  BOTTOM w0.508: C147.2 R60.2
UNNAMED_9_CAP_I224_N2: length 1.2
  TOP w0.508: C144.2 100.18,51.62 100.18,51.11 R61.2
UNNAMED_9_CAP_I306_N1: length 12
  TOP w0.762: 80.54,47.44 C149.1 81.44,46.39 ; 84.34,40.37 L5.2 ; L5.2 84.34,43.09 ; L5.2 83.56,41.73 ; 80.54,44.9 C150.1 ; C150.1 81.44,43.85 ; C150.1 81.44,45.96 ; 79.22,46.81 E3.1 ; E3.1 78.33,47.64 ; E3.1 80.11,47.64
  BOTTOM w0.305: R64.2 v1(83.16,43.13)
UNNAMED_9_CN5P3SHLD_I255_N6: length 11.2
  TOP w0.635: 107.69,39.61 P2.SH3 106.27,38.84 ; 106.31,30.49 P2.SH1 107.69,29.73
  BOTTOM w0.635: 107.69,29.68 P2.SH1 106.56,30.49 ; 107.69,39.66 P2.SH3 106.4,38.84
  BOTTOM w0.762: 104.81,28.33 R55.1 ; R55.1 104.81,30.24 ; R55.1 105.71,29.28
  vias: v1(104.37,30.55) v1(104.37,28.01) v1(105.38,30.55) v1(105.38,28.01) v1(106.27,35.76) v1(106.27,34.62) v1(106.27,33.47)
UNNAMED_9_CN5P3SHLD_I256_N6: length 11.6
  TOP w0.635: P3.SH1 106.21,48.27 ; P3.SH3 106.15,56.62
  TOP w0.762: P3.SH3 107.69,57.39 ; 107.69,47.51 P3.SH1
  BOTTOM w0.635: P3.SH1 106.43,48.27 ; P3.SH3 106.27,56.62
  BOTTOM w0.762: R58.1 105.59,47.06 ; R58.1 104.68,48.02 ; R58.1 104.68,46.11 ; P3.SH3 107.69,57.44 ; 107.69,47.46 P3.SH1
  vias: v1(104.37,48.33) v1(104.37,45.79) v1(105.38,48.33) v1(105.38,45.79) v1(106.27,53.67) v1(106.27,52.45) v1(106.27,51.13)
UNNAMED_9_FERRITE_I303_N1: length 4.3
  TOP w0.762: 85.06,31.51 E7.1 ; E7.1 85.95,30.68 ; E7.1 86.84,31.51 ; 87.69,31.77 Q3.2 88.64,31.01
UNNAMED_9_ICNCP339_I277_EN: length 2.7
  TOP w0.203: R69.1 101.97,50.47 R68.2 101.97,51.9 102.4,52.34 U8.C2
UNNAMED_9_ICNCP339_I278_EN: length 3.5
  TOP w0.254: U9.C2 100.93,37.29 100.57,37.65 R70.2 v1(100.43,38.43)
  BOTTOM w0.254: Q2.3 99.52,38.43 v1(100.43,38.43)
UNNAMED_9_RES_I270_N1: length 2.9
  BOTTOM w0.254: Q2.1 100.1,34.78 R67.1 100.05,34.73 R66.2
UNNAMED_11_ICUSB3320C_I29_RBIAS: length 2
  TOP w0.127: v1(79,28.52) U15.24
  BOTTOM w0.127: v1(79,28.52) 79,27.81 R77.1
UNNAMED_11_ICUSB3320C_I29_REFCL: length 1.7
  TOP w0.254: R82.1 77.8,29.12 U15.26
UNNAMED_11_ICUSB3320C_I29_VBUS: length 2.4
  TOP w0.254: R75.2 80.49,27.37 80.49,27.12 79.84,26.48 U15.22
UNNAMED_11_ICXC7Z010_I11_PSMI_1: length 3.7
  TOP w0.127: U4.D13 v2(57.93,28.95)
  BOTTOM w0.127: v2(57.93,28.95) 57.93,26.97 58.16,26.74 R85.1
UNNAMED_11_ICXC7Z010_I11_PSMIO4: length 1.7
  TOP w0.127: v2(59.54,29.74) U4.B12
  BOTTOM w0.127: v2(59.54,29.74) 59.93,29.35 59.93,29.24 R86.1
UNNAMED_11_RES_I67_N2: length 1.6
  TOP w0.305: Y1.3 79.34,30.7 R82.2
USB_OTG_N: length 33.1
  TOP w0.102: 101.31,35.13 100.31,35.13 99.4,34.22 99.4,29.78 97.02,27.39 85.58,27.39 83.06,24.86 79.42,24.86 79.31,24.98 U15.19 ; 101.31,35.13 103.99,35.13 104.18,35.32 P2.2 ; 101.31,35.13 101.32,35.14 D2.C
USB_OTG_P: length 33.2
  TOP w0.102: 102.39,34.86 D1.C 102.53,34.86 ; 102.39,34.86 102.53,34.86 ; 102.39,34.86 100.42,34.86 99.67,34.11 99.67,29.66 97.13,27.12 85.69,27.12 83.17,24.6 79.41,24.6 79.29,24.48 U15.18 ; 102.53,34.86 104,34.86 104.19,34.67 P2.3
USR_LED: length 67.1
  TOP w0.127: U4.K13 v2(52.33,28.95)
  L6_SIG w0.127: v2(52.33,28.95) U4.K13 53.63,29.35 53.93,29.65 53.93,30.45 54.43,30.95 59.23,30.95 59.63,31.35 69.24,31.35 70.24,32.35 75.44,32.35 78.34,29.45 80.95,29.45 85.55,24.84 85.55,15.54 91.79,9.29 v1(100.73,9.29)
  BOTTOM w0.127: Q4.1 v1(100.73,9.29)
VTT_0P75: length 29.8
  TOP w0.203: 39.98,53.03 U14.3
  TOP w0.889: 41.97,54.47 C79.1 41.12,53.67
  BOTTOM w0.305: 51.49,53.27 R37.2 R31.2 ; 50.42,46.84 R28.2 ; R28.2 R30.2 ; R28.2 49.96,47.25 ; R35.2 52.72,57.5 ; R35.2 R16.2 ; R35.2 R39.2 ; 42.81,54.94 R43.1 42.25,54.38 ; 46.6,47.81 R20.2 ; R20.2 46.6,48.73 ; R20.2 46.19,48.27 ; R16.2 51.92,57.5 ; R16.2 R23.2 ; 52.02,46.84 R21.2 ; R21.2 R30.2 ; R21.2 R38.2 ; R30.2 51.22,46.84 ; R22.2 46.6,52.33 ; R22.2 R29.2 ; R22.2 46.19,51.87 ; 46.19,50.27 R18.2 ; R18.2 R27.2 ; R18.2 46.6,50.27 R29.2 ; R39.2 R33.2 ; R39.2 53.52,57.5 ; R33.2 54.78,57.09 ; R33.2 54.32,57.5 ; R23.2 R24.2 50.32,57.5 ; R23.2 51.12,57.5 ; 44.41,57.05 C101.1 ; C101.1 44.41,58.16 ; C101.1 44.97,57.6 ; 51.49,52.47 R32.2 ; 48.46,47.25 R19.2 ; R19.2 49.37,47.25 ; R19.2 48.92,46.84 ; R29.2 46.19,51.07 ; R17.2 R34.2 ; R17.2 R26.2 46.09,55.68 ; R17.2 46.09,54.88 ; R34.2 46.09,54.07 ; R34.2 46.5,53.61 ; 46.6,49.01 R27.2 ; R27.2 46.19,49.47 ; 51.49,51.67 R36.2 ; R25.2 48.12,57.5
  vias: v1(42.52,54.05) v1(42.52,53.29) v1(43.28,54.05) v1(43.28,53.29)
VTTVREF: length 79.7
  TOP w0.152: 52.02,51.17 v2(52.02,50.27)
  TOP w0.203: U14.6 36.65,53.83 36.51,53.97 35.52,53.97 C84.1
  TOP w0.305: U2.M8 v2(52.02,50.27) ; U2.H1 v2(55.22,55.87) ; U4.F4 v2(56.33,36.95)
  TOP w0.508: 52.02,51.17 52.02,51.77 51.12,52.67 46.92,52.67 45.82,53.77 45.82,58.62 ; 45.82,58.62 48.36,58.62 49.25,57.73 53.69,57.73 54.58,58.62 v1(55.22,58.62) v2(55.22,55.87) ; 45.82,58.62 37.05,58.62 36.23,57.8 C81.1 35.41,55 C84.1
  BOTTOM w0.152: 55.92,38.16 55.92,37.36 56.33,36.96 v2(56.33,36.95) 56.72,37.34 56.72,38.16 56.32,38.56 55.92,38.16
  BOTTOM w0.305: C102.1 52.5,49.78 v2(52.02,50.27) ; C63.2 55.71,55.87 v2(55.22,55.87) ; 57.92,40.26 C99.2
  BOTTOM w0.508: 56.32,38.56 56.52,38.76 56.52,39.66 57.12,40.26 57.92,40.26 57.92,40.37 63.33,45.78 63.33,56.78 62.53,57.58 57.53,57.58 56.49,58.62 v1(55.22,58.62)

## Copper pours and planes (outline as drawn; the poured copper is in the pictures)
1.0V on TOP: 75.66,11.76 86.84,11.76 86.84,17.47 73.25,17.47 73.25,14.17
1.35V on TOP: 78.71,55.06 85.44,55.06 85.95,54.56 90.65,54.56 90.65,57.73 78.71,57.73
1V8 on TOP (solid shape): 38.61,10.59 38.8,10.59 38.9,10.54 39,10.53 39.69,10.53 39.73,10.53 39.85,10.54 39.85,10.49 39.91,10.49 39.89,10.37 39.89,10.33 39.89,9.64 39.89,9.59 39.9,9.54 39.93,9.48 39.93,9.22 41.76,9.22 41.76,8.96 41.74,8.96 41.74,8.93 41.68,8.86 41.21,8.86 41.21,8.05 41.68,8.05 41.74,7.98 41.74,7.95 41.76,7.95 41.76,6.68 39.34,6.68 37.56,8.46 37.56,11.38 38.61,11.38
1V8 on TOP (solid shape): 17.02,10.64 17.15,10.64 17.27,10.56 17.42,10.53 18.1,10.53 18.14,10.53 18.26,10.54 18.26,10.49 18.32,10.49 18.3,10.37 18.3,10.33 18.3,9.64 18.3,9.59 18.31,9.54 18.34,9.48 18.34,9.22 19.86,9.22 19.86,9.27 19.98,9.26 20.05,9.27 20.13,9.24 20.17,9.17 20.17,8.96 20.15,8.96 20.15,8.93 20.09,8.86 19.62,8.86 19.62,8.05 20.09,8.05 20.15,7.98 20.15,7.95 20.17,7.95 20.17,6.68 18.51,6.68 15.97,9.22 15.97,11.38 17.02,11.38
1V8 on TOP: 34.64,13.03 31.34,13.03 31.34,11.5 31.85,11 31.85,9.09 34.64,9.09
1V8 on TOP: 82.01,48.97 82.01,51.76 78.2,51.76 77.7,51.25 77.7,48.71 80.87,48.71 81.13,48.97
1V8 on TOP: 39.34,51.13 39.34,44.14 41.76,44.14 41.76,51.13
1V8 on BOTTOM: 66.27,26.87 63.6,26.87 63.6,33.09 66.27,33.09
1V8 on L8_PWR: 59.66,4.26 59.66,11.25 47.78,11.25 42.7,6.17 17.75,6.17 17.75,13.15 20.74,13.15 21.69,14.11 36.8,14.11 36.8,21.41 39.34,21.41 39.34,49.98 69.64,49.98 72.81,53.16 84.43,53.16 84.43,4.26
1V35 on TOP: 78.08,52.52 78.08,57.73 75.54,57.73 75.54,51.38 76.93,51.38
1V35 on TOP: 55.73,41.96 55.73,44.17 58.32,44.17 58.32,41.96
1V35 on TOP: 67.54,52.78 63.73,52.78 63.73,55.32 67.54,55.32
1V35 on L3_PWR: 46.14,33.79 38.71,41.23 38.71,59.51 50.93,59.51 52.28,59.26 53.63,59.51 77.44,59.51 77.44,50.62 72.55,50.62 65.7,43.77 65.7,35.7 57.25,35.7 55.67,37.28 51.09,37.28 51.09,33.79
GND on TOP: 82.65,44.14 82.65,52.4 80.11,52.4 79.98,52.27 78.59,52.27 78.59,54.56 84.94,54.56 84.94,51 91.03,51 91.41,51.38 92.3,51.38 92.3,52.14 95.6,52.14 95.6,48.97 92.3,48.97 92.3,49.6 91.16,49.6 91.09,49.67 92.16,49.67 92.16,50.08 90.84,50.08 90.84,49.86 84.81,49.86 84.81,44.14 ; 2 cut-outs
GND on TOP: 108.5,27.01 108.5,20.9 108.5,10.08 108.5,8.6 107.49,5.87 104.95,4.43 104.08,4.29 80.14,1.63 56.08,0.64 56.08,6.28 52.28,10.08 48.48,6.28 48.48,0.68 27.87,1.62 7.34,3.8 3.99,4.28 0.64,4.78 0.64,15.52 1.27,15.52 1.27,21.69 6.83,21.69 6.83,24.2 1.27,24.2 1.27,30.38 0.64,30.38 0.64,38.96 1.27,38.96 1.27,45.13 6.96,45.13 6.96,47.65 1.27,47.65 1.27,53.82 0.64,53.82 0.64,64.55 3.99,65.06 7.34,65.54 8.5,65.69 8.5,62.48 26.28,62.48 26.28,63.74 48.48,63.74 48.48,63.06 52.28,59.26 56.08,63.06 56.08,68.7 80.14,67.71 104.08,65.04 104.95,64.9 107.49,63.47 108.5,60.73 108.5,57.99 107.41,57.99 107.41,47.32 108.5,47.32 108.5,40.98 104.86,40.98 104.86,40.08 103.73,40.08 103.73,37.16 104.35,37.16 104.35,33.24 103.33,32.22 103.33,27.01 ; 56 cut-outs
GND on BOTTOM: 104.08,4.29 80.14,1.63 56.08,0.64 56.08,6.28 52.28,10.08 48.48,6.28 48.48,0.68 27.87,1.62 7.34,3.8 3.99,4.28 0.64,4.78 0.64,15.52 1.27,15.52 1.27,30.38 0.64,30.38 0.64,38.96 1.27,38.96 1.27,53.82 0.64,53.82 0.64,64.55 1.7,64.72 1.7,64.72 16.68,66.68 31.72,67.98 31.72,65.22 48.48,65.22 48.48,63.06 48.6,62.12 48.94,61.24 48.94,59.89 49.78,59.89 49.78,60.2 51.4,59.36 53.21,59.38 53.21,58.95 55.01,58.95 55.01,59.15 55.65,59.15 55.65,61.31 55.97,62.16 56.08,63.06 56.08,68.7 80.14,67.71 104.08,65.04 104.95,64.9 107.49,63.47 108.5,60.73 108.5,59.46 108.48,59.46 108.48,58.76 104.86,58.76 104.86,56.22 104.35,55.72 104.35,50.64 103.33,49.62 103.33,44.79 108.48,44.79 108.48,40.98 104.86,40.98 104.86,37.81 104.35,37.3 104.35,33.24 103.33,32.22 103.33,27.01 108.48,27.01 108.48,26.92 108.5,26.92 108.5,15.52 108.5,10.08 108.5,8.6 107.49,5.87 104.95,4.43 ; 63 cut-outs
GND on L2_GND: 104.08,4.29 80.14,1.63 56.08,0.64 56.08,6.28 52.28,10.08 48.48,6.28 48.48,0.68 24.49,1.9 0.64,4.78 0.64,15.52 1.27,15.52 1.27,30.38 0.64,30.38 0.64,38.96 1.27,38.96 1.27,53.82 0.64,53.82 0.64,64.55 24.49,67.44 48.48,68.66 48.48,63.06 52.28,59.26 56.08,63.06 56.08,68.7 80.14,67.71 104.08,65.04 104.95,64.9 107.49,63.47 108.5,60.73 108.5,58.76 104.86,58.76 104.86,54.57 104.22,53.94 104.22,50.38 103.33,49.49 103.33,44.79 108.5,44.79 108.5,40.98 104.86,40.98 104.86,36.67 104.35,36.16 104.35,33.24 103.33,32.22 103.33,27.01 108.5,27.01 108.5,15.52 108.5,8.6 107.49,5.87 104.95,4.43 ; 2 cut-outs
GND on L3_PWR: 66.33,35.7 66.33,43.5 72.81,49.98 78.08,49.98 78.08,60.14 54.71,60.14 55.72,61.45 56.08,63.06 56.08,68.7 80.14,67.71 104.08,65.04 104.95,64.9 107.26,63.72 108.45,61.41 89.51,61.41 89.51,41.09 84.43,41.09 84.43,35.7
GND on L3_PWR: 104.08,4.29 80.14,1.63 56.08,0.64 56.08,6.28 52.28,10.08 48.48,6.28 48.48,0.68 24.49,1.9 0.64,4.78 0.64,15.52 1.27,15.52 1.27,30.38 0.64,30.38 0.64,38.96 1.27,38.96 1.27,53.82 0.64,53.82 0.64,64.55 24.49,67.44 48.48,68.66 48.48,63.06 48.84,61.45 49.84,60.14 38.07,60.14 38.07,51.25 23.47,51.25 23.47,43.5 25.88,41.09 30.96,41.09 35.53,36.52 35.53,23.31 26.64,23.31 26.64,10.17 26.83,9.98 46.33,9.98 46.33,15.69 61.57,15.69 61.57,8.07 108.47,8.07 107.32,5.67 104.95,4.43
GND on L4_GND, L7_GND, L9_GND: 104.08,4.29 80.14,1.63 56.08,0.64 56.08,6.28 52.28,10.08 48.48,6.28 48.48,0.68 24.49,1.9 0.64,4.78 0.64,15.52 1.27,15.52 1.27,30.38 0.64,30.38 0.64,38.96 1.27,38.96 1.27,53.82 0.64,53.82 0.64,64.55 24.49,67.44 48.48,68.66 48.48,63.06 52.28,59.26 56.08,63.06 56.08,68.7 80.14,67.71 104.08,65.04 104.95,64.9 107.49,63.47 108.5,60.73 108.5,58.76 104.86,58.76 104.86,54.57 104.22,53.94 104.22,50.38 103.33,49.49 103.33,44.79 108.5,44.79 108.5,40.98 104.86,40.98 104.86,36.67 104.35,36.16 104.35,33.24 103.33,32.22 103.33,27.01 108.5,27.01 108.5,15.52 108.5,8.6 107.49,5.87 104.95,4.43
GND on L5_SIG: 104.08,4.29 80.14,1.63 56.08,0.64 56.08,6.28 52.28,10.08 48.48,6.28 48.48,0.68 24.49,1.9 0.64,4.78 0.64,15.52 1.27,15.52 1.27,30.38 0.64,30.38 0.64,38.96 1.27,38.96 1.27,53.82 0.64,53.82 0.64,64.55 24.49,67.44 48.48,68.66 48.48,63.06 52.28,59.26 56.08,63.06 56.08,68.7 80.14,67.71 104.08,65.04 104.95,64.9 107.49,63.47 108.5,60.73 108.5,58.76 103.33,58.76 103.33,44.79 108.5,44.79 108.5,40.98 104.35,40.98 104.35,33.24 103.33,32.22 103.33,27.01 108.5,27.01 108.5,15.52 108.5,8.6 107.49,5.87 104.95,4.43 ; 31 cut-outs
GND on L6_SIG: 104.08,4.29 80.14,1.63 56.08,0.64 56.08,6.28 52.28,10.08 48.48,6.28 48.48,0.68 24.49,1.9 0.64,4.78 0.64,15.52 1.27,15.52 1.27,30.38 0.64,30.38 0.64,38.96 1.27,38.96 1.27,53.82 0.64,53.82 0.64,64.55 24.49,67.44 48.48,68.66 48.48,63.06 52.28,59.26 56.08,63.06 56.08,68.7 80.14,67.71 104.08,65.04 104.95,64.9 107.49,63.47 108.5,60.73 108.5,58.76 104.86,58.76 104.86,54.45 104.22,53.81 104.22,50.38 103.33,49.49 103.33,44.79 108.5,44.79 108.5,40.98 104.35,40.98 104.35,33.24 103.33,32.22 103.33,27.01 108.5,27.01 108.5,15.52 108.5,8.6 107.49,5.87 104.95,4.43 ; 25 cut-outs
GND on L8_PWR: outline of 90 points within 0.64,0.64 108.5,68.7 ; 1 cut-out
VCCPINT on TOP: 56.03,21.74 64.18,21.74 64.18,24.09 56.03,24.09
VCCPINT on TOP: 72.62,18.49 72.62,14.17 69.19,14.17 69.19,18.49
VCCPINT on L3_PWR: 68.55,13.79 68.55,16.33 46.33,16.33 46.33,33.16 51.73,33.16 51.73,36.65 55.4,36.65 56.99,35.06 77.44,35.06 77.44,13.79
VDD_INTERFACE on TOP: 31.98,13.66 31.98,17.22 32.1,17.35 32.1,17.97 34.64,17.97 34.64,13.66
VDD_INTERFACE on L8_PWR: 27.91,14.74 27.91,27.76 29.69,27.76 36.04,21.41 36.17,21.41 36.17,14.74
VIN on TOP: 87.35,35.25 87.35,32.97 83.79,32.97 83.79,38.94 86.97,38.94 86.97,35.63
VIN on TOP: 93.32,48.59 93.32,41.22 91.16,41.22 91.16,47.44 92.3,48.59 ; 1 cut-out
VIN on TOP: 93.32,52.46 92.23,52.46 91.16,53.54 91.16,60.02 93.32,60.02 ; 1 cut-out
VIN on TOP: 97.25,14.55 99.79,14.55 99.79,22.17 97.38,22.17 97.38,20.01 97.51,19.89 97.51,18.74 97.25,18.49
VIN on TOP: 37.06,51.76 37.06,52.4 35.91,52.4 35.41,51.89 35.41,49.98 36.55,49.98 36.93,50.37 36.93,51.64 ; 1 cut-out
VIN on L3_PWR: 62.2,8.71 62.2,15.69 67.92,15.69 67.92,13.15 78.08,13.15 78.08,35.06 85.06,35.06 85.06,40.46 90.14,40.46 90.14,60.78 108.5,60.78 108.5,60.73 108.5,57.47 108.5,55.88 107.56,55.88 106.81,55.57 106.5,54.82 106.81,54.07 107.56,53.76 108.5,53.76 108.5,51.13 107.56,51.13 106.81,50.82 106.5,50.07 106.81,49.32 107.56,49.01 108.5,49.01 108.5,38.1 107.56,38.1 106.81,37.79 106.5,37.04 106.81,36.29 107.56,35.98 108.5,35.98 108.5,33.35 107.56,33.35 106.81,33.04 106.5,32.29 106.81,31.54 107.56,31.23 108.5,31.23 108.5,29.65 108.5,8.71
VIN on L8_PWR: 85.06,34.74 85.06,53.79 72.55,53.79 69.37,50.62 38.71,50.62 38.71,49.35 34.9,49.35 34.9,55.89 39.16,60.14 49.84,60.14 52.28,59.26 54.71,60.14 90.14,60.14 90.14,34.74
VIN_5V_USB on TOP: 94.33,30.81 96.62,30.81 96.62,36.4 93.06,36.4 93.06,34.87 94.33,34.87
VIN_5V_USB on TOP: 101.95,37.67 101.95,37.7 102.93,37.7 102.93,38.1 101.95,38.1 101.95,39.44 103.86,39.44 103.86,38.43 103.1,37.67
VIN_5V_USB on TOP: 100.43,52.91 100.18,53.16 100.18,54.81 101.57,54.81 102.08,54.3 102.08,54.04 101.56,54.04 101.56,52.92 102.08,52.92 102.08,52.91
VIN_5V_USB on L8_PWR: 93.32,30.3 93.32,57.6 103.48,57.6 103.48,42.55 104.11,41.92 104.11,34.56 103.48,33.92 103.48,30.3
VIN_5V_USB_DATA on TOP: 102.59,35.76 101.95,36.4 101.95,36.92 102.93,36.92 102.93,37 102.93,37 102.93,37.4 101.95,37.4 101.95,37.41 103.48,37.41 103.86,37.03 103.86,35.76
VIN_5V_USB_POWER on TOP: 102.21,52.91 105.24,52.91 105.24,53.94 104.22,53.94 103.97,54.19 103.97,54.81 102.72,54.81 102.21,54.3 ; 1 cut-out
(no net) on TOP: 37.56,12.01 37.56,16.33 42.52,16.33 42.52,15.57 41.88,14.93 41.88,14.55 39.98,14.55 39.98,14.35 41.88,14.35 41.88,13.41 41.76,13.28 39.85,13.28 39.85,12.01 38.91,12.01 38.91,13.18 38.61,13.18 38.61,12.01
(no net) on TOP: 39.34,6.68 37.56,8.46 37.56,11.76 39.85,11.76 39.85,10.49 41.76,10.49 41.76,9.62 39.93,9.62 39.93,9.22 41.76,9.22 41.76,6.68 ; 1 cut-out
(no net) on TOP: 20.17,10.49 18.26,10.49 18.26,11.76 15.97,11.76 15.97,9.22 18.51,6.68 20.17,6.68 ; 2 cut-outs
(no net) on TOP: 15.97,12.01 15.97,16.33 20.93,16.33 20.93,15.57 20.29,14.93 20.29,14.54 18.39,14.54 18.39,14.24 20.29,14.24 20.29,13.41 20.17,13.28 18.26,13.28 18.26,12.01 17.17,12.01 17.17,13.03 17.32,13.03 17.32,13.18 17.02,13.18 17.02,12.01
1P3_SUPPLY_A on TOP (solid shape): 38.06,15.43 39.36,15.43 39.36,16.33 39.72,16.33 39.72,16.32 39.75,16.32 39.82,16.25 39.82,15.78 40.64,15.78 40.64,16.25 40.71,16.32 40.74,16.32 40.74,16.33 40.99,16.33 40.99,16.32 41.02,16.32 41.09,16.25 41.09,15.78 41.91,15.78 41.91,16.25 41.98,16.32 42.01,16.32 42.01,16.33 42.52,16.33 42.52,15.57 41.88,14.93 41.88,14.55 39.98,14.55 39.98,14.37 39.91,14.26 39.89,14.13 39.89,13.44 39.89,13.4 39.91,13.28 39.85,13.28 39.85,13.23 39.73,13.24 39.69,13.24 39,13.24 38.9,13.23 38.8,13.18 38.61,13.18 38.61,12.01 37.56,12.01 37.56,13.65 38.47,13.65 38.47,14.95 37.56,14.95 37.56,16.33 38.06,16.33
1P3_SUPPLY_A on L3_PWR: 27.28,10.61 27.28,22.68 36.17,22.68 36.17,36.78 31.22,41.73 26.14,41.73 24.1,43.77 24.1,50.62 38.07,50.62 38.07,40.96 45.69,33.34 45.69,10.61
1P3_SUPPLY_B on TOP (solid shape): 16.47,15.43 17.77,15.43 17.77,16.33 18.13,16.33 18.13,16.32 18.16,16.32 18.23,16.25 18.23,15.78 19.05,15.78 19.05,16.25 19.12,16.32 19.15,16.32 19.15,16.33 19.4,16.33 19.4,16.32 19.43,16.32 19.5,16.25 19.5,15.78 20.32,15.78 20.32,16.25 20.39,16.32 20.42,16.32 20.42,16.33 20.93,16.33 20.93,15.57 20.29,14.93 20.29,14.54 18.39,14.54 18.39,14.38 18.33,14.26 18.3,14.13 18.3,13.44 18.3,13.39 18.32,13.34 18.32,13.28 18.26,13.28 18.26,13.23 18.2,13.23 18.15,13.24 18.1,13.24 17.41,13.24 17.31,13.23 17.21,13.18 17.02,13.18 17.02,12.01 15.97,12.01 15.97,13.65 16.88,13.65 16.88,14.95 15.97,14.95 15.97,16.33 16.47,16.33
1P3_SUPPLY_B on L8_PWR: 11.4,13.79 11.4,46.81 34.9,46.81 34.9,41.09 19.66,41.09 19.66,21.41 27.28,21.41 27.28,14.74 21.43,14.74 20.48,13.79
SYNC on TOP: 87.86,11.76 90.27,11.76 90.27,19.12 88.49,19.12 87.86,18.49 ; 1 cut-out
TX1A_N on TOP (solid shape): 22.51,30.06 22.72,29.91 22.98,29.85 23.1,29.85 23.1,29 21.09,29 20.48,29.61 20.48,30.06
TX1A_P on TOP (solid shape): 23.1,30.69 22.77,30.69 22.55,30.47 20.48,30.47 20.48,30.93 21.09,31.54 23.1,31.54
UNNAMED_2_ADP2164_I29_EN on TOP: 91.29,20.01 94.46,20.01 94.46,21.16 91.29,21.16 ; 1 cut-out
UNNAMED_2_ADP2164_I29_PVIN1 on TOP: 90.78,14.93 90.78,17.47 90.65,17.6 90.65,17.9 91.03,17.9 91.08,17.96 91.08,18.36 90.88,18.36 90.65,18.13 90.65,19.12 91.29,19.12 91.29,19.76 94.33,19.76 95.6,18.49 95.6,14.93 ; 1 cut-out
UNNAMED_4_ICTPS51206_I44_VLDOIN on TOP: 38.58,52.52 39.6,52.52 39.85,52.27 39.85,51.64 41.63,51.64 41.63,52.4 41.3,52.73 38.58,52.73
UNNAMED_9_ADM1177_I23_GATE on TOP: 87.86,33.35 89.89,33.35 89.89,36.27 88.11,36.27 87.86,36.01
UNNAMED_9_ADM1177_I23_SENSE on TOP: 90.55,34.24 90.55,30.81 93.83,30.81 93.83,34.24
UNNAMED_9_ADP2114_I196_SW1 on TOP: 91.99,49.35 91.99,48.78 90.27,47.06 85.44,47.06 85.44,49.35 ; 1 cut-out
UNNAMED_9_ADP2114_I196_SW3 on TOP: 85.44,51.51 85.44,53.79 90.36,53.79 91.69,52.46 91.99,52.46 91.99,51.51 91.35,51.51 91.35,52.57 90.84,52.57 90.84,51.51
UNNAMED_9_CAP_I163_N1 on TOP: 85.44,39.82 88.75,39.82 88.75,43.51 90.14,43.51 90.65,44.02 90.65,46.3 85.44,46.3
UNNAMED_9_CAP_I306_N1 on TOP: 84.68,39.82 84.68,43.63 81.89,43.63 81.89,48.08 77.7,48.08 77.7,43.76 81.63,39.82
UNNAMED_9_CN5P3SHLD_I255_N6 on TOP, BOTTOM, L2_GND, L4_GND, L7_GND, L9_GND: 103.97,27.65 103.97,31.57 105.38,31.57 105.51,31.7 105.51,32.46 106.02,32.97 106.02,36.65 105.49,37.17 105.49,40.35 108.5,40.35 108.5,38.1 107.56,38.1 106.81,37.79 106.5,37.04 106.81,36.29 107.56,35.98 108.5,35.98 108.5,33.35 107.56,33.35 106.81,33.04 106.5,32.29 106.81,31.54 107.56,31.23 108.5,31.23 108.5,30.28 108.47,30.28 108.47,27.65
UNNAMED_9_CN5P3SHLD_I256_N6 on TOP: 103.97,45.43 103.97,49.35 105.38,49.35 105.51,49.48 105.51,50.24 106,50.73 106,54.95 105.49,55.46 105.49,58.13 108.5,58.13 108.5,55.88 107.56,55.88 106.81,55.57 106.5,54.82 106.81,54.07 107.56,53.76 108.5,53.76 108.5,51.13 107.56,51.13 106.81,50.82 106.5,50.07 106.81,49.32 107.56,49.01 108.5,49.01 108.5,48.06 108.47,48.06 108.47,45.43
UNNAMED_9_CN5P3SHLD_I256_N6 on BOTTOM: 103.99,45.41 103.99,49.35 105.38,49.35 105.51,49.48 105.51,50.24 106.02,50.75 106.02,54.43 105.51,54.94 105.51,58.13 108.5,58.13 108.5,55.88 107.56,55.88 106.81,55.57 106.5,54.82 106.81,54.07 107.56,53.76 108.5,53.76 108.5,51.13 107.56,51.13 106.81,50.82 106.5,50.07 106.81,49.32 107.56,49.01 108.5,49.01 108.5,48.06 108.47,48.06 108.47,45.41
UNNAMED_9_CN5P3SHLD_I256_N6 on L2_GND: 103.97,45.43 103.97,49.35 105.38,49.35 105.51,49.48 105.51,50.24 106.02,50.75 106.02,54.43 105.49,54.95 105.49,58.13 108.5,58.13 108.5,55.88 107.56,55.88 106.81,55.57 106.5,54.82 106.81,54.07 107.56,53.76 108.5,53.76 108.5,51.13 107.56,51.13 106.81,50.82 106.5,50.07 106.81,49.32 107.56,49.01 108.5,49.01 108.5,48.06 108.47,48.06 108.47,45.43
UNNAMED_9_CN5P3SHLD_I256_N6 on L4_GND, L7_GND, L9_GND: 103.97,45.43 103.97,49.35 105.38,49.35 105.51,49.48 105.51,50.27 106,50.76 106,54.45 105.49,54.95 105.49,58.13 108.5,58.13 108.5,55.88 107.56,55.88 106.81,55.57 106.5,54.82 106.81,54.07 107.56,53.76 108.5,53.76 108.5,51.13 107.56,51.13 106.81,50.82 106.5,50.07 106.81,49.32 107.56,49.01 108.5,49.01 108.5,48.06 108.47,48.06 108.47,45.43
UNNAMED_9_FERRITE_I303_N1 on TOP: 89.13,32.2 89.13,30.55 88.36,29.79 84.3,29.79 84.3,32.2
VTT_0P75 on TOP: 39.6,52.93 43.53,52.93 43.53,54.94 40.23,54.94 40.23,53.41 39.95,53.13 39.6,53.13
VTT_0P75 on BOTTOM: 44.17,58.62 44.17,55.7 43.66,55.19 42.01,55.19 42.01,52.88 42.61,52.27 44.31,52.27 44.71,51.87 44.71,46.07 52.22,46.07 52.22,47.47 46.72,47.47 46.72,52.02 49.07,52.02 49.7,51.38 52.17,51.38 52.17,53.87 49.92,53.87 49.22,53.17 48.35,53.17 46.82,54.7 46.82,56.08 46.84,56.08 46.84,57.1 49.63,57.1 49.88,56.84 55.09,56.84 55.09,57.86 54.33,58.62 50.39,58.62 49.5,59.51 45.06,59.51

Small or netless copper shapes (teardrops, artwork), in the pictures only: 2 on TOP

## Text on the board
BOTTOM: SECONDARY SIDE
TOP: ADRV9363-W/USB | PRIMARY SIDE | 08-043758 REV A Z
Ref Des/Assembly Top: K | A | ASSEMBLY NOTES: | 1. DS1 AND DS2 ARE RIGHT ANGLE LEDs
Ref Des/Silkscreen Top: K | A
DIMENSION: " " | SEE DETAIL A | 0.0330 | (2PLCS) | 0.0165 | 0.0395 | 0.0790 | RADIUS | FULL | SCALE: NONE | DETAIL A | 0.1870 | EDGE | PCB | REF | x2 | MOLEX47590-0001_CUTOUT-DETAIL | DIA MAX
PAGE_OUTLINE: CUSTOMER EVAL BOARD Z
User.15: PREPREG 2.98MILS | PREPREG 2.9MILS | CORE 3MILS | NOTE: ALL IMPEDANCE TOLERANCE +/-10% | LAYER | L1 | L5 | L6 | L10 | SE = SINGLE ENDED, DP = DIFFERENTIAL PAIR | 100 OHMS DP | IMPEDANCE | 50 OHMS SE | 40 OHMS SE | 90 OHMS DP | 80 OHMS DP | REFERENCE | L4,L7 | L2 | L4 | L9 | LINE WIDTH | 19MILS | 6.5MILS | 4MILS | 9MILS | 4.5MILS | 5.5MILS | 5MILS | SPACE | 7MILS | 6MILS | N/A | IMPEDANCE TABLE
User.17: L2 GND | 08-      -07
User.18: L3 PWR | 08-      -08
User.19: L4 GND | 08-      -09
User.20: L5 SIG | 08-      -10
User.22: L6 SIG | 08-      -11
User.23: L7 GND | 08-      -12
User.24: L8 PWR | 08-      -13
User.25: L9 GND | 08-      -14
User.45: FIGURE | SIZE | 8.0 | 10.0 | 28.0 | 126.0 | 34.0x26.0 | 51.0x24.0 | FINISHED HOLES IN MILS | ALL UNITS ARE IN MILS | PLATED | NON-PLATED | QTY | 583 | 797 | 10 | 4 | TOLERANCE/NOTES
